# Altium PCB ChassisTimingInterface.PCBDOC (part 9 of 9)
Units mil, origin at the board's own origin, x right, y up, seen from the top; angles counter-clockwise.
Board outline 7007.87 x 4368.85 mil, 10 copper layers (Top Layer, Int1 (GND), Int2 (Sign), Int3 (Sign), Int4 (PWR), Int5 (GND), Int6 (Sign), Int7 (Sign), Int8 (GND), Bottom Layer), stack 54.89 mil thick; 537 components, 525 nets, 2288 pads, 1306 vias.
Unrouted connection lines stored in the file: 373.
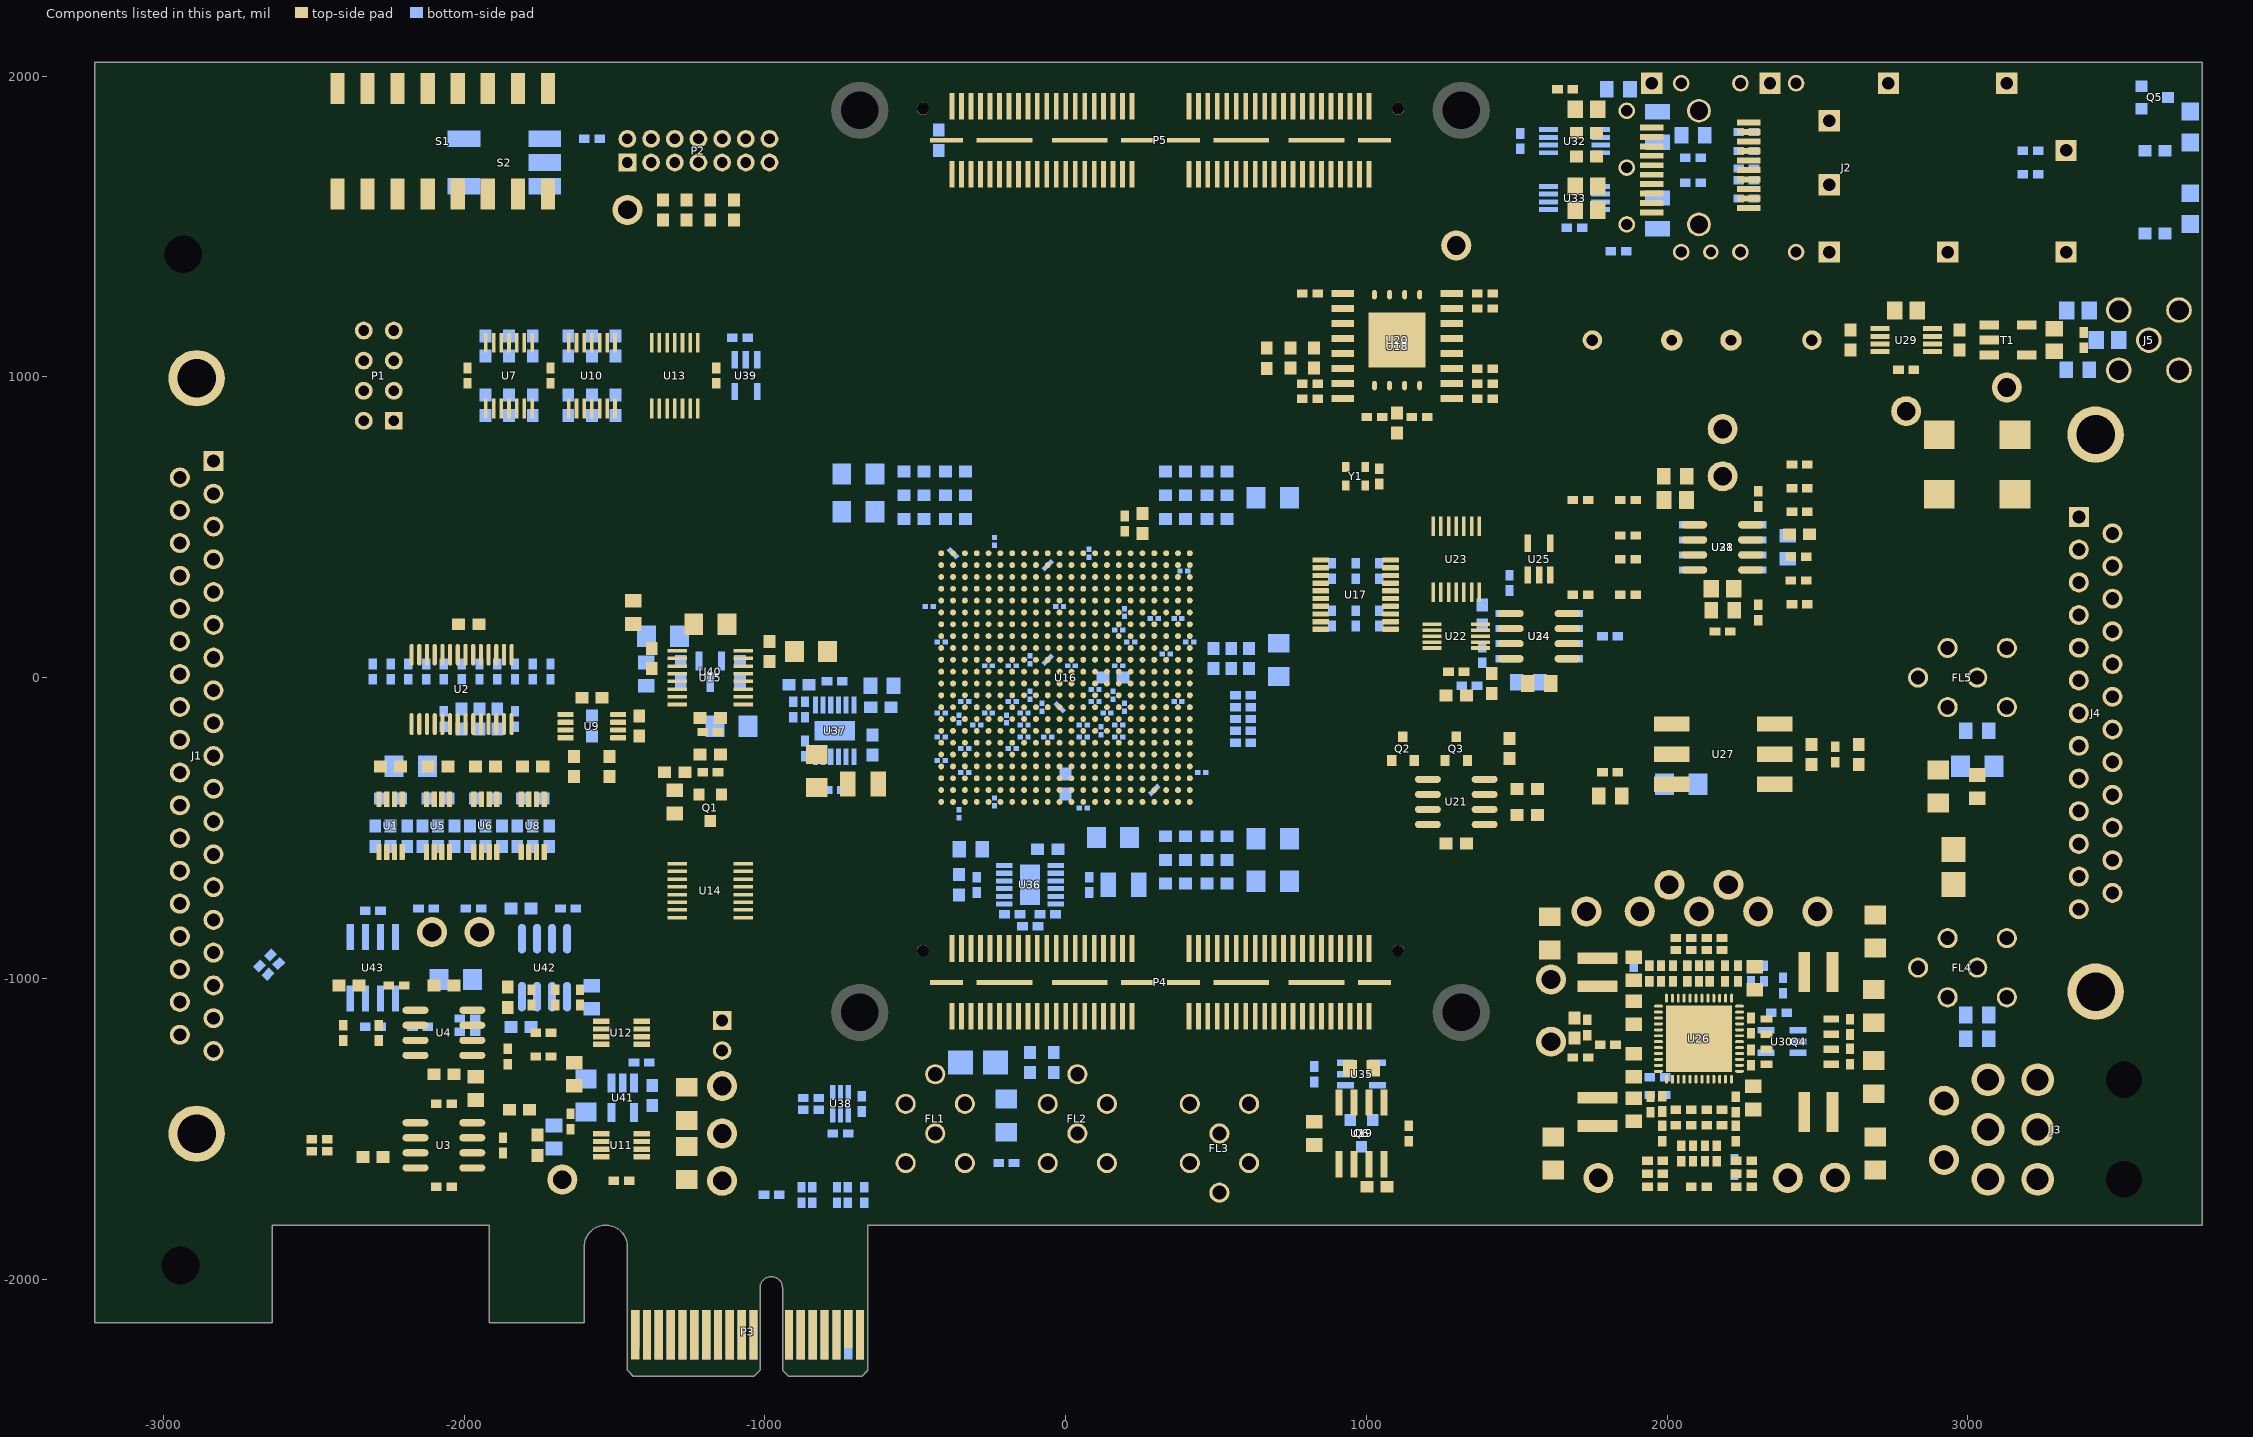
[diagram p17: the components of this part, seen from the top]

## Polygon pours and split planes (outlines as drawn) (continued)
no net on Bottom Layer "NONET_L10_P092" (solid, pour order 92): 2299.21,-1082.68
NetC129_2 on Bottom Layer "NETC129_2_L10_P044" (solid, pour order 44): 169.29,-748.03 169.29,-622.05 137.8,-590.55 137.8,-472.44 64.9,-472.44 64.9,-681.1 90.55,-681.1 106.3,-696.85 106.3,-748.03
GND on Bottom Layer "GND_L10_P053" (solid, pour order 53): -877.95,-125.98 -877.95,-145.67 -921.26,-188.98 -921.26,-228.35 -846.46,-228.35 -807.09,-188.98 -807.09,-145.67 -838.58,-145.67 -858.27,-125.98
XADCVCC on Bottom Layer "XADCVCC_L10_P090" (solid, pour order 90): -94.49,-74.8 -94.49,-51.18 ccw(c-114.17,-51.18) -114.17,-31.5 -432.79,-31.5 cw(c-432.79,121.25) -540.8,13.24 ccw(c-613.37,-59.32) -613.38,43.31 -870.08,43.31 cw(c-870.08,59.05) -885.83,59.3 ccw(c-1383.11,67) -885.83,74.8 -883.46,74.8 -593.14,74.8 cw(c-593.13,-16.96) -528.23,47.92 -507.68,27.36 ccw(c-432.12,102.92) -432.12,-3.94 -46.57,-3.94 cw(c-46.56,-68.83) -0.68,-22.95 cw(c-40.31,-62.59) 15.75,-62.6 15.75,-74.8 cw(c0,-74.81) 0,-90.55 -78.74,-90.55 cw(c-78.74,-74.8)
XADCGND on Bottom Layer "XADCGND_L10_P087" (solid, pour order 87): -110.24,-122.05 -110.24,-169.29 ccw(c-94.49,-169.3) -94.49,-185.04 -1.62,-185.04 ccw(c-1.62,-152.55) 21.37,-175.51 62.55,-134.26 ccw(c23.38,-95.14) 78.74,-95.14 78.74,3.94 ccw(c58.98,3.94) 58.98,23.7 -381.95,23.7 -414.51,23.7 cw(c-414.53,107.22) -481.18,56.89 ccw(c-592.84,-27.27) -539.84,102.12 ccw(c-601.12,-46.64) -601.31,114.25 -870,114.25 ccw(c-870.02,98.44) -885.83,98.43 -885.83,80.01 -585.35,80.12 cw(c-585.28,-8.37) -522.7,54.19 -499.35,30.85 ccw(c-434.34,95.91) -434.34,3.94 -43.25,3.94 cw(c-43.24,-62.91) 23.6,-62.92 23.6,-74.82 cw(c-7.78,-74.84) -7.8,-106.23 -94.41,-106.22 ccw(c-94.42,-122.04)
no net on Bottom Layer "NONET_L10_P086" (solid, pour order 86): -19.69,-59.06
no net on Bottom Layer "NONET_L10_P085" (solid, pour order 85): -944.88,118.11
GND on Bottom Layer "GND_L10_P084" (solid, pour order 84): 858.27,417.32 984.25,543.31 1200.79,543.31 1200.79,354.33 1102.36,354.33 1102.36,374.02 858.27,374.02
GND on Bottom Layer "GND_L10_P082" (solid, pour order 82): 311.02,688.98 311.02,704.72 354.33,748.03 362.2,748.03 362.2,688.98
no net on Bottom Layer "NONET_L10_P081" (solid, pour order 81): -421.26,755.91
no net on Bottom Layer "NONET_L10_P080" (solid, pour order 80): -807.09,582.68
AGND on Bottom Layer "AGND_L10_P076" (solid, pour order 76): 2244.09,370.08 2200.79,326.77 2200.79,271.65 2314.96,157.48 2381.89,157.48 2437.01,212.6 2437.01,409.45 2366.14,409.45 2326.77,370.08
AGND on Bottom Layer "AGND_L10_P074" (solid, pour order 74): 1803.15,157.48 1787.4,173.23 1712.6,173.23 1712.6,102.36 1787.4,102.36 1803.15,118.11
P10V on Bottom Layer "P10V_L10_P073" (solid, pour order 73): 1555.12,590.55 1544.88,590.55 ccw(c1544.88,490.55) 1444.88,490.55 1444.88,330.71 1507.87,330.71 1507.87,484.25 cw(c1555.12,484.25) 1555.12,531.5
P10V on Bottom Layer "P10V_L10_P068" (solid, pour order 68): 2224.41,590.55 ccw(c2224.41,570.87) 2204.72,570.87 2204.72,464.57 ccw(c2224.41,464.57) 2224.41,444.88 2421.26,444.88 ccw(c2421.26,464.57) 2440.94,464.57 2440.94,570.87 ccw(c2421.26,570.87) 2421.26,590.55
no net on Bottom Layer "NONET_L10_P067" (solid, pour order 67): 2224.41,590.55
AGND on Bottom Layer "AGND_L10_P062" (solid, pour order 62): 1287.4,157.48 ccw(c1299.21,157.48) 1299.21,145.67 1318.9,145.67 ccw(c1318.9,157.48) 1330.71,157.48 1330.71,204.72 cw(c1346.46,204.72) 1346.46,220.47 1417.32,220.47 1417.32,271.65 1354.33,271.65 ccw(c1354.33,204.72) 1287.4,204.72
AGND on Bottom Layer "AGND_L10_P057" (solid, pour order 57): 1625.98,11.81 1625.98,-51.18 1570.87,-106.3 1468.5,-106.3 1468.5,-62.99 1535.43,-62.99 1555.12,-43.31 1555.12,11.81
P10V on Bottom Layer "NONET_L10_P054" (solid, pour order 54): 1523.62,-43.32 1523.62,11.81 1562.99,51.18 1594.49,51.18 1594.49,74.78 1429.11,74.78 1417.32,62.99 1350.39,62.99 1350.39,-43.32 1421.26,-43.32 1476.39,-43.32
no net on Bottom Layer "NONET_L10_P047" (solid, pour order 47): -1622.05,-1543.31
no net on Bottom Layer "NONET_L10_P046" (solid, pour order 46): -1559.06,-1303.15
no net on Bottom Layer "NONET_L10_P045" (solid, pour order 45): -1653.54,-1173.23
no net on Bottom Overlay "NONET_L-01_P-001" (solid): -1492.13,-1555.12
P5V on Int7 (Sign) "P5V_L08_P052" (solid, pour order 52): -2637.8,-1653.54 -2637.8,-1051.18 -2326.77,-740.16 -1641.73,-740.16 -1338.58,-1043.31 -1338.58,-1708.66 -1716.54,-1708.66 -1771.65,-1653.54
AVCC1V8 on Int7 (Sign) "AVCC1V8_L08_P079" (solid, pour order 79): 1673.23,-1204.72 1673.23,-1385.83 -279.53,-1385.83 -1527.56,-137.79 -1527.56,177.17 -1358.27,177.17 -1358.27,-66.93 -220.47,-1204.73
no net on Int7 (Sign) "NONET_L08_P078" (solid, pour order 78): 1692.91,-1141.73
N12V on Int2 (Sign) "N12V_L03_P048" (solid, pour order 48): 480.22,-1712.61 480.22,-1122.85 -1259.04,-1122.85 -1641.73,-740.16 -2326.77,-740.16 -2637.8,-1051.18 -2637.8,-1653.54 -1771.65,-1653.54 -1716.54,-1708.66 -1421.26,-1708.66
no net on MultiLayer "NONET_L-01_P-001" (solid): -2255.91,102.36
GND on Int1 (GND) (split plane): 161 vertices, not listed, extent -3208.25,-2302.74 3119.99,2025.92
VREF2V5 on Int1 (GND) (split plane): -1505.99,-1698.73 -1712.42,-1698.73 -1764.63,-1646.52 -1766.69,-1644.95 -1769.08,-1643.95 -1771.65,-1643.62 -2155.43,-1643.62 -2155.43,-998.12 -1505.99,-998.12
VCC2 on Int1 (GND) (split plane): -1309.14,212.42 -1309.14,161.59 -1424.34,46.39 -1425.92,44.33 -1426.91,41.94 -1427.25,39.37 -1427.25,0 -1427.25,-255.91 -1427.25,-369.9 -1539.55,-482.2 -1574.8,-482.2 -2279.35,-482.2 -2387.71,-373.84 -2387.71,58.88 -2200.61,245.98 -1342.69,245.98
EXT12V on Int1 (GND) (split plane): 3297.16,-1303.32 3297.16,-1673.23 3297.16,-1688.8 3259.67,-1726.29 3155.69,-1726.29 2864.26,-1434.86 2864.26,-1067.1 2917.5,-1013.86 3007.7,-1013.86
12V on Int1 (GND) (split plane): 3759.43,-1800.77 -186.92,-1800.77 -186.92,-1441.12 -130.78,-1384.97 -74.63,-1328.82 1476.38,-1328.82 1478.95,-1328.49 1481.34,-1327.49 1483.4,-1325.92 1562.14,-1247.18 1563.72,-1245.12 1564.71,-1242.73 1565.05,-1240.16 1565.05,-944.88 1564.71,-942.31 1563.72,-939.92 1562.82,-938.75 1562.14,-937.86 1325.92,-701.64 1210.71,-586.44 1210.71,-476.55 1263.95,-423.31 2519.69,-423.31 2522.25,-422.97 2524.65,-421.98 2526.7,-420.41 2664.5,-282.61 2684.19,-262.93 2684.19,-262.92 3136.94,189.83 3137.63,190.72 3138.52,191.89 3139.51,194.28 3139.85,196.85 3139.85,255.91 3139.85,968.5 3139.51,971.07 3138.52,973.47 3136.94,975.52 2432.22,1680.25 2430.16,1681.83 2427.77,1682.82 2425.2,1683.16 968.68,1683.16 797.33,1854.51 797.33,2025.92 3759.43,2025.92
XADCVCC on Int1 (GND) (split plane): -817.01,9.93 -1407.4,9.93 -1407.4,35.26 -1295.1,147.55 -817.01,147.55
VCC1V8 on Int1 (GND) (split plane): 777.47,-78.74 777.47,-133.68 251.79,-659.36 181.28,-659.36 29.61,-507.7 29.61,-59.06 29.27,-56.49 28.28,-54.09 26.7,-52.04 24.65,-50.46 22.25,-49.47 19.68,-49.13 -433.07,-49.13 -435.64,-49.47 -438.03,-50.46 -440.09,-52.04 -538.52,-150.46 -540.09,-152.52 -541.09,-154.91 -541.42,-157.48 -541.42,-350.22 -574.98,-383.77 -659.36,-383.77 -659.36,-63.17 -507.7,88.5 777.47,88.5
VCC on Int4 (PWR) (split plane): 3759.43,-1800.77 -657.48,-1800.77 -661.4,-1801.16 -665.17,-1802.3 -668.65,-1804.16 -671.69,-1806.66 -674.19,-1809.7 -676.05,-1813.18 -677.19,-1816.95 -677.58,-1820.87 -677.58,-2294.83 -685.49,-2302.74 -912.94,-2302.74 -920.85,-2294.83 -920.85,-2029.53 -920.86,-2029.38 -921.22,-2023.09 -922.3,-2016.73 -924.08,-2010.54 -926.55,-2004.58 -929.67,-1998.94 -933.4,-1993.68 -937.69,-1988.87 -942.5,-1984.58 -947.76,-1980.85 -953.4,-1977.73 -959.36,-1975.26 -965.55,-1973.48 -971.91,-1972.4 -978.35,-1972.04 -984.78,-1972.4 -991.14,-1973.48 -997.33,-1975.26 -1003.29,-1977.73 -1008.93,-1980.85 -1014.19,-1984.58 -1019,-1988.87 -1023.3,-1993.68 -1027.03,-1998.94 -1030.15,-2004.58 -1032.61,-2010.54 -1034.4,-2016.73 -1035.48,-2023.09 -1035.83,-2029.38 -1035.84,-2029.53 -1035.84,-2294.83 -1043.76,-2302.74 -1428.68,-2302.74 -1436.6,-2294.83 -1436.6,-1892.72 -1436.61,-1892.55 -1436.96,-1884.7 -1438,-1876.75 -1439.74,-1868.92 -1442.15,-1861.27 -1445.22,-1853.86 -1448.92,-1846.75 -1453.23,-1839.98 -1458.11,-1833.62 -1463.53,-1827.71 -1469.45,-1822.29 -1475.81,-1817.41 -1482.57,-1813.1 -1489.69,-1809.39 -1497.1,-1806.32 -1504.75,-1803.91 -1512.58,-1802.18 -1520.53,-1801.13 -1528.54,-1800.78 -1536.56,-1801.13 -1544.51,-1802.18 -1552.34,-1803.91 -1559.99,-1806.32 -1567.4,-1809.39 -1574.51,-1813.1 -1581.28,-1817.41 -1587.64,-1822.29 -1593.55,-1827.71 -1598.97,-1833.62 -1603.85,-1839.98 -1608.16,-1846.75 -1611.87,-1853.86 -1614.94,-1861.27 -1617.35,-1868.92 -1619.08,-1876.75 -1620.13,-1884.7 -1620.47,-1892.55 -1620.49,-1892.72 -1620.49,-2125.57 -1895.26,-2125.57 -1895.26,-1820.87 -1895.64,-1816.95 -1896.79,-1813.18 -1898.64,-1809.7 -1901.14,-1806.66 -1904.19,-1804.16 -1907.66,-1802.3 -1911.43,-1801.16 -1915.35,-1800.77 -2637.8,-1800.77 -2641.72,-1801.16 -2645.49,-1802.3 -2648.96,-1804.16 -2652.01,-1806.66 -2654.51,-1809.7 -2656.36,-1813.18 -2657.51,-1816.95 -2657.89,-1820.87 -2657.89,-2125.57 -3208.25,-2125.57 -3208.25,2025.92 3759.43,2025.92
AVTT on Int4 (PWR) (split plane): -383.94,-137.8 -383.6,-140.36 -382.61,-142.76 -381.04,-144.81 -378.98,-146.39 -376.59,-147.38 -374.02,-147.72 -344.57,-147.72 -344.57,-334.65 -344.57,-816.84 -974.32,-816.84 -974.32,-29.61 -383.94,-29.61
AVCC on Int4 (PWR) (split plane): -187.09,39.37 -187.09,-19.68 -187.09,-177.17 -187.09,-216.54 -187.09,-255.91 -187.09,-816.84 -324.72,-816.84 -324.72,-334.65 -324.72,-137.8 -325.06,-135.23 -326.05,-132.83 -327.63,-130.78 -329.68,-129.2 -332.08,-128.21 -334.65,-127.87 -364.09,-127.87 -364.09,-19.68 -364.43,-17.12 -365.42,-14.72 -367,-12.67 -369.05,-11.09 -371.45,-10.1 -374.02,-9.76 -974.32,-9.76 -974.32,521.57 -187.09,521.57
VCCINT on Int4 (PWR) (split plane): 88.5,-59.06 88.84,-61.62 89.83,-64.02 91.41,-66.07 93.46,-67.65 95.86,-68.64 98.43,-68.98 665.18,-68.98 800.07,-203.87 1545.19,-948.99 1545.19,-1015.75 1545.53,-1018.32 1546.52,-1020.71 1548.1,-1022.77 1587.47,-1062.14 1589.52,-1063.72 1591.92,-1064.71 1594.49,-1065.05 2035.26,-1065.05 2583.53,-1613.32 2612.12,-1641.91 2612.12,-1684.86 2591.41,-1705.58 2582.5,-1714.48 2535.61,-1714.48 2395.73,-1574.6 2395.42,-1572.23 2394.42,-1569.84 2392.85,-1567.78 2390.79,-1566.21 2388.4,-1565.21 2386.03,-1564.9 1995.21,-1174.08 1993.15,-1172.51 1990.76,-1171.51 1988.19,-1171.18 1500.17,-1171.18 1148.75,-819.75 1146.7,-818.17 1144.3,-817.18 1141.73,-816.84 -167.24,-816.84 -167.24,-216.54 -167.24,-177.17 -167.24,-29.61 88.5,-29.61
P10V on Int4 (PWR) (split plane): 1505.82,397.46 1505.82,157.48 1506.16,154.91 1507.15,152.52 1508.73,150.46 1592.43,66.75 1592.43,59.23 1558.88,25.68 1456.87,25.68 1446.94,35.61 1446.94,397.46 1456.87,407.4 1495.89,407.4
VCC1V8 on Int4 (PWR) (split plane): 977.23,-7.02 1355.18,-384.97 1355.19,-384.97 1675.11,-704.9 1675.11,-1045.19 1598.6,-1045.19 1565.05,-1011.64 1565.05,-944.88 1564.71,-942.31 1563.72,-939.92 1562.14,-937.86 814.11,-189.83 676.31,-52.04 674.26,-50.46 671.86,-49.47 669.29,-49.13 108.35,-49.13 108.35,-19.68 108.01,-17.12 107.02,-14.72 105.44,-12.67 103.39,-11.09 100.99,-10.1 98.43,-9.76 -167.24,-9.76 -167.24,521.57 448.64,521.57
GND on Int5 (GND) (split plane): 3759.43,-1800.77 -657.48,-1800.77 -661.4,-1801.16 -665.17,-1802.3 -668.65,-1804.16 -671.69,-1806.66 -674.19,-1809.7 -676.05,-1813.18 -677.19,-1816.95 -677.58,-1820.87 -677.58,-2294.83 -685.49,-2302.74 -912.94,-2302.74 -920.85,-2294.83 -920.85,-2029.53 -920.86,-2029.38 -921.22,-2023.09 -922.3,-2016.73 -924.08,-2010.54 -926.55,-2004.58 -929.67,-1998.94 -933.4,-1993.68 -937.69,-1988.87 -942.5,-1984.58 -947.76,-1980.85 -953.4,-1977.73 -959.36,-1975.26 -965.55,-1973.48 -971.91,-1972.4 -978.35,-1972.04 -984.78,-1972.4 -991.14,-1973.48 -997.33,-1975.26 -1003.29,-1977.73 -1008.93,-1980.85 -1014.19,-1984.58 -1019,-1988.87 -1023.3,-1993.68 -1027.03,-1998.94 -1030.15,-2004.58 -1032.61,-2010.54 -1034.4,-2016.73 -1035.48,-2023.09 -1035.83,-2029.38 -1035.84,-2029.53 -1035.84,-2294.83 -1043.76,-2302.74 -1428.68,-2302.74 -1436.6,-2294.83 -1436.6,-1892.72 -1436.61,-1892.55 -1436.96,-1884.7 -1438,-1876.75 -1439.74,-1868.92 -1442.15,-1861.27 -1445.22,-1853.86 -1448.92,-1846.75 -1453.23,-1839.98 -1458.11,-1833.62 -1463.53,-1827.71 -1469.45,-1822.29 -1475.81,-1817.41 -1482.57,-1813.1 -1489.69,-1809.39 -1497.1,-1806.32 -1504.75,-1803.91 -1512.58,-1802.18 -1520.53,-1801.13 -1528.54,-1800.78 -1536.56,-1801.13 -1544.51,-1802.18 -1552.34,-1803.91 -1559.99,-1806.32 -1567.4,-1809.39 -1574.51,-1813.1 -1581.28,-1817.41 -1587.64,-1822.29 -1593.55,-1827.71 -1598.97,-1833.62 -1603.85,-1839.98 -1608.16,-1846.75 -1611.87,-1853.86 -1614.94,-1861.27 -1617.35,-1868.92 -1619.08,-1876.75 -1620.13,-1884.7 -1620.47,-1892.55 -1620.49,-1892.72 -1620.49,-2125.57 -1895.26,-2125.57 -1895.26,-1820.87 -1895.64,-1816.95 -1896.79,-1813.18 -1898.64,-1809.7 -1901.14,-1806.66 -1904.19,-1804.16 -1907.66,-1802.3 -1911.43,-1801.16 -1915.35,-1800.77 -2637.8,-1800.77 -2641.72,-1801.16 -2645.49,-1802.3 -2648.96,-1804.16 -2652.01,-1806.66 -2654.51,-1809.7 -2656.36,-1813.18 -2657.51,-1816.95 -2657.89,-1820.87 -2657.89,-2125.57 -3208.25,-2125.57 -3208.25,2025.92 3759.43,2025.92
BGND on Int5 (GND) (split plane): -1215.68,-1180.25 -1192.06,-1203.87 -1190,-1205.45 -1187.61,-1206.44 -1185.04,-1206.78 11.64,-1206.78 88.5,-1283.64 88.5,-1302.12 88.5,-1307.09 88.5,-1440.94 88.5,-1496.06 88.84,-1498.63 89.83,-1501.03 91.41,-1503.08 130.78,-1542.45 131.67,-1543.14 132.83,-1544.03 135.23,-1545.02 137.8,-1545.36 204.72,-1545.36 207.29,-1545.02 209.69,-1544.03 211.74,-1542.45 378.13,-1376.07 440.77,-1376.07 553.06,-1488.36 553.06,-1726.29 470.56,-1726.29 470.56,-1562.99 470.56,-1547.24 470.22,-1544.67 469.23,-1542.28 467.65,-1540.22 436.15,-1508.73 434.1,-1507.15 431.7,-1506.16 429.13,-1505.82 370.08,-1505.82 367.51,-1506.16 365.12,-1507.15 363.06,-1508.73 208.49,-1663.3 157.48,-1663.3 155.51,-1663.56 153.54,-1663.3 118.29,-1663.3 -9.76,-1535.26 -9.76,-1338.58 -10.1,-1336.01 -11.09,-1333.62 -11.98,-1332.46 -12.67,-1331.56 -59.91,-1284.32 -61.97,-1282.74 -64.36,-1281.75 -66.93,-1281.41 -1161.42,-1281.41 -1163.99,-1281.75 -1166.38,-1282.74 -1168.44,-1284.32 -1207.81,-1323.69 -1209.38,-1325.74 -1210.38,-1328.14 -1210.71,-1330.71 -1210.71,-1385.83 -1210.38,-1388.4 -1209.38,-1390.79 -1207.81,-1392.85 -1168.44,-1432.22 -1167.54,-1432.9 -1166.38,-1433.79 -1163.99,-1434.79 -1161.42,-1435.12 -1090.73,-1435.12 -1053.23,-1472.62 -1053.23,-1566.75 -1090.73,-1604.25 -1165.35,-1604.25 -1167.92,-1604.58 -1170.32,-1605.58 -1172.37,-1607.15 -1207.81,-1642.59 -1209.38,-1644.64 -1210.38,-1647.04 -1210.71,-1649.61 -1210.71,-1676.99 -1232.46,-1698.73 -1712.42,-1698.73 -1764.63,-1646.52 -1766.69,-1644.95 -1769.08,-1643.95 -1771.65,-1643.62 -2627.87,-1643.62 -2627.87,-1059.23 -2422.11,-853.48 -2318.72,-750.08 -1645.84,-750.08
XADCGND on Int5 (GND) (split plane): -1180.25,209.52 -1089.7,118.96 -1088.8,118.28 -1087.64,117.39 -1085.25,116.4 -1082.68,116.06 -820.95,116.06 -820.95,59.23 -830.88,49.3 -944.88,49.3 -947.45,48.96 -949.85,47.97 -951.9,46.39 -953.48,44.33 -954.47,41.94 -954.81,39.37 -954.81,-19.69 -954.47,-22.25 -953.48,-24.65 -951.9,-26.7 -919.38,-59.23 -919.38,-125.81 -937.18,-143.62 -1035.43,-143.62 -1038,-143.95 -1040.4,-144.95 -1042.45,-146.52 -1102.54,-206.61 -1177.17,-206.61 -1179.73,-206.95 -1182.13,-207.94 -1184.19,-209.52 -1602.54,-627.87 -2291.16,-627.87 -2387.71,-531.32 -2387.71,58.88 -2200.61,245.98 -1216.71,245.98
AGND on Int5 (GND) (split plane): 3179.05,566.75 3179.05,118.11 3179.05,63.17 3083.53,-32.35 2515.57,-600.31 1815.14,-600.31 1683.16,-468.33 1683.16,-275.59 1682.82,-273.02 1681.83,-270.63 1680.93,-269.46 1680.25,-268.57 1562.14,-150.46 1560.08,-148.88 1557.69,-147.89 1555.12,-147.55 1323.01,-147.55 1269.77,-94.31 1269.77,212.42 1362.38,305.03 1909.45,305.03 1912.02,305.37 1914.41,306.36 1916.47,307.94 1995.21,386.68 1996.1,387.84 1996.79,388.74 1997.08,389.44 1997.78,391.13 1998.12,393.7 1998.12,665.18 2110.41,777.47 2968.33,777.47
VDD on Int8 (GND) (split plane): 3759.43,-1800.77 -657.48,-1800.77 -661.4,-1801.16 -665.17,-1802.3 -668.65,-1804.16 -671.69,-1806.66 -674.19,-1809.7 -676.05,-1813.18 -677.19,-1816.95 -677.58,-1820.87 -677.58,-2294.83 -685.49,-2302.74 -912.94,-2302.74 -920.85,-2294.83 -920.85,-2029.53 -920.86,-2029.38 -921.22,-2023.09 -922.3,-2016.73 -924.08,-2010.54 -926.55,-2004.58 -929.67,-1998.94 -933.4,-1993.68 -937.69,-1988.87 -942.5,-1984.58 -947.76,-1980.85 -953.4,-1977.73 -959.36,-1975.26 -965.55,-1973.48 -971.91,-1972.4 -978.35,-1972.04 -984.78,-1972.4 -991.14,-1973.48 -997.33,-1975.26 -1003.29,-1977.73 -1008.93,-1980.85 -1014.19,-1984.58 -1019,-1988.87 -1023.3,-1993.68 -1027.03,-1998.94 -1030.15,-2004.58 -1032.61,-2010.54 -1034.4,-2016.73 -1035.48,-2023.09 -1035.83,-2029.38 -1035.84,-2029.53 -1035.84,-2294.83 -1043.76,-2302.74 -1428.68,-2302.74 -1436.6,-2294.83 -1436.6,-1892.72 -1436.61,-1892.55 -1436.96,-1884.7 -1438,-1876.75 -1439.74,-1868.92 -1442.15,-1861.27 -1445.22,-1853.86 -1448.92,-1846.75 -1453.23,-1839.98 -1458.11,-1833.62 -1463.53,-1827.71 -1469.45,-1822.29 -1475.81,-1817.41 -1482.57,-1813.1 -1489.69,-1809.39 -1497.1,-1806.32 -1504.75,-1803.91 -1512.58,-1802.18 -1520.53,-1801.13 -1528.54,-1800.78 -1536.56,-1801.13 -1544.51,-1802.18 -1552.34,-1803.91 -1559.99,-1806.32 -1567.4,-1809.39 -1574.51,-1813.1 -1581.28,-1817.41 -1587.64,-1822.29 -1593.55,-1827.71 -1598.97,-1833.62 -1603.85,-1839.98 -1608.16,-1846.75 -1611.87,-1853.86 -1614.94,-1861.27 -1617.35,-1868.92 -1619.08,-1876.75 -1620.13,-1884.7 -1620.47,-1892.55 -1620.49,-1892.72 -1620.49,-2125.57 -1895.26,-2125.57 -1895.26,-1820.87 -1895.64,-1816.95 -1896.79,-1813.18 -1898.64,-1809.7 -1901.14,-1806.66 -1904.19,-1804.16 -1907.66,-1802.3 -1911.43,-1801.16 -1915.35,-1800.77 -2637.8,-1800.77 -2641.72,-1801.16 -2645.49,-1802.3 -2648.96,-1804.16 -2652.01,-1806.66 -2654.51,-1809.7 -2656.36,-1813.18 -2657.51,-1816.95 -2657.89,-1820.87 -2657.89,-2125.57 -3208.25,-2125.57 -3208.25,2025.92 3759.43,2025.92
N5V on Int8 (GND) (split plane): -1368.2,-1027.73 -1368.2,-1698.73 -1712.42,-1698.73 -1764.63,-1646.52 -1766.69,-1644.95 -1769.08,-1643.95 -1771.65,-1643.62 -2627.87,-1643.62 -2627.87,-1059.23 -2318.72,-750.08 -1645.84,-750.08

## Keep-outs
Top Layer:
  rectangle: -3228.35,1208.66 -2728.35,2013.78
  rectangle: -657.48,-1820.87 3779.53,-1781.5
  region: -3228.35,-2147.65 -2637.8,-2147.65 ccw(c-2637.8,-2145.67) -2635.81,-2145.67 -2635.81,-1822.85 -1917.34,-1822.85 -1917.34,-2009.84 ccw(c-1915.35,-2009.84) -1915.35,-2011.83 -1600.39,-2011.83 ccw(c-1600.39,-2009.84) -1598.41,-2009.84 ccw(c-1600.39,-2009.84) -1598.41,-2009.82 -1598.41,-1892.72 cw(c-1528.54,-1892.72) -1458.68,-1892.72 ccw(c-1456.69,-1892.72) -1454.71,-1892.72 -1454.71,-1781.5 ccw(c-1456.69,-1781.5) -1456.69,-1779.51 -3228.35,-1779.51 ccw(c-3228.35,-1781.5) -3230.33,-1781.5 -3230.33,-2145.67 ccw(c-3228.35,-2145.67)
Bottom Layer:
  rectangle: -657.48,-1820.87 3372.05,-1781.5
  rectangle: -3228.35,1208.66 -2728.35,2013.78
  region: -3228.35,-2147.65 -2637.8,-2147.65 ccw(c-2637.8,-2145.67) -2635.81,-2145.67 -2635.81,-1822.85 -1917.34,-1822.85 -1917.34,-2009.84 ccw(c-1915.35,-2009.84) -1915.35,-2011.83 -1600.39,-2011.83 ccw(c-1600.39,-2009.84) -1598.41,-2009.84 ccw(c-1600.39,-2009.84) -1598.41,-2009.82 -1598.41,-1892.72 cw(c-1528.54,-1892.72) -1458.68,-1892.72 ccw(c-1456.69,-1892.72) -1454.71,-1892.72 -1454.71,-1781.5 ccw(c-1456.69,-1781.5) -1456.69,-1779.51 -3228.35,-1779.51 ccw(c-3228.35,-1781.5) -3230.33,-1781.5 -3230.33,-2145.67 ccw(c-3228.35,-2145.67)
Top Solder:
  rectangle: -1915.35,-2145.67 -1600.39,-2009.84
Bottom Solder:
  rectangle: -1915.35,-2145.67 -1600.39,-2009.84
KeepOutLayer:
  rectangle: -1915.35,-2145.67 -1600.39,-2009.84

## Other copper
Top Layer:
  rectangle net NetC67_1: 2460.63,-322.83 2574.8,-263.78
  rectangle net AGND: 2460.63,-248.03 2574.8,-185.04
  rectangle net NetC38_2: 1818.9,-421.26 1874.02,-299.21
  rectangle net 12V: 1846.46,-1277.06 1917.78,-1259.84
  rectangle net SENSE.SENS_18_P: 1704.72,-952.76 1917.32,-862.2
  rectangle net AGND: 2216.54,141.73 2330.71,165.35
  rectangle net N5V: -1909.45,-1125.98 -1826.77,-1070.87
  rectangle net GND: -2019.69,893.7 -1960.63,996.06
  rectangle net NetC25_2: -751.97,-397.64 -669.29,-311.02
  rectangle net NetC25_2: -885.83,-397.64 -696.85,-334.65
  rectangle net GND: -834.65,-244.09 -779.53,-141.73
  rectangle net GND: -921.26,-287.4 -779.53,-224.41
  rectangle net VDD: -822.83,19.69 -783.46,59.06
  rectangle net GND: 2240.16,-976.38 2275.59,-917.32
  rectangle net AVCC1V8: 1566.93,-1210.63 1661.42,-1149.1
  rectangle net AVCC1V8: 1566.93,-1156.49 1678.52,-1110.24
  rectangle net GND: 2078.74,-972.44 2129.92,-905.51
  rectangle net GND: 1968.5,-972.44 1992.13,-901.57
  rectangle net VDD: 1811.02,-1251.97 1826.77,-1205.71
  rectangle net GND: 2216.54,-1559.06 2259.84,-1523.62
  rectangle net GND: 1720.47,-1277.06 1795.28,-1171.26
  rectangle net AVCC1V8: 1656,-1156.49 1751.97,-1110.24
  rectangle net GND: 2062.99,-1452.76 2149.61,-1421.26
  rectangle net GND: 1952.76,-1559.06 1996.06,-1523.62
  rectangle net GND: 1859.52,-1372.04 1918.57,-1303.15
  rectangle net 12V: 1843.01,-1175.19 1916.83,-1129.42
  rectangle net GND: 1862.2,-1052.16 1917.32,-986.22
  rectangle net GND: 2259.84,-1474.41 2314.96,-1415.35
  rectangle net 12V: 2259.84,-1379.92 2314.96,-1316.93
  rectangle net 12V: 2263.78,-1078.74 2318.9,-1015.75
  rectangle net VCC: 1566.93,-1744.09 1834.65,-1590.55
  rectangle net GND: 1859.52,-1421.26 1918.57,-1353.34
  rectangle net GND: 1862.2,-1096.46 1917.32,-1030.81
  rectangle net SENSE.SENS_10_P: 2515.75,-1578.74 2755.91,-1326.77
  rectangle net VCCINT: 2507.87,-1744.09 2755.91,-1594.49
  rectangle net SENSE.SENS_25_P: 2514.76,-1098.43 2755.91,-851.86
  rectangle net SENSE.SENS_33_P: 1566.93,-1577.89 1917.57,-1450.79
  rectangle net NetC49_1: 1566.93,-1441.92 1843.85,-1283.45
  rectangle net NetC48_1: 1700.79,-1082.68 1846.46,-965.54
  rectangle net VDD: 2448.82,-834.65 2755.91,-726.38
  rectangle net AGND: 1543.31,106.3 1606.3,173.23
  rectangle net P10V: 2212.6,496.06 2358.27,586.61
  rectangle net GND: 1598.43,311.02 1649.61,374.02
  rectangle net AGND: 2854.33,556.1 2956.69,858.27
  rectangle net GND: -1464.57,240.16 -1409.45,303.15
  rectangle net AVCC1V8: -1480.32,102.36 -1409.45,200.79
  rectangle net AGND: 1311.02,-106.3 1561.02,-31.5
  rectangle net VCC1V8: -647.75,-397.64 -570.87,-311.02
  rectangle net XADCGND: -1535.43,-374.02 -1496.06,-307.09
  rectangle net VCC2: -1653.54,-374.02 -1614.17,-307.09
  rectangle net AGND: 2287.4,125.98 2354.33,208.66
  rectangle net AGND: 2279.53,602.36 2326.77,685.04
  rectangle net AGND: 2448.82,598.43 2531.5,661.42
  rectangle net AGND: 2448.82,681.1 2531.5,736.22
  rectangle net GND: 1562.99,1929.13 1653.54,1984.25
  rectangle net AGND: 1748.03,-421.26 1803.15,-299.21
  rectangle net NetC35_2: 1669.29,1696.85 1724.41,1988.19
  rectangle net GND: 1744.09,1858.27 1818.9,1921.26
  rectangle net GND: 1665.35,1523.62 1724.41,1665.35
  rectangle net XADCGND: -1259.84,-275.59 -1192.91,-236.22
  rectangle net VCC: -1157.48,141.73 -1070.87,212.6
  rectangle net VCC2: -1385.83,141.73 -1204.72,212.6
  rectangle net VCC2: -1972.44,153.54 -1905.51,200.79
  rectangle net XADCGND: -2062.99,153.54 -1996.06,200.79
  rectangle net GND: 2704.72,1188.98 2783.46,1251.97
  rectangle net GND: 2704.72,996.06 2787.4,1051.18
  rectangle net VCC: -1740.16,1011.81 -1685.04,1133.86
  rectangle net VCC: -2019.69,1011.81 -1960.63,1133.86
  rectangle net GND: -1740.16,874.02 -1685.04,996.06
  rectangle net VCC: -1196.85,893.7 -1133.86,996.06
  rectangle net GND: -1192.91,1011.81 -1133.86,1133.86
  rectangle net BGND: -1661.42,-1425.2 -1606.3,-1334.65
  rectangle net VREF2V5: -1724.41,-1145.67 -1669.29,-1070.87
  rectangle net VREF2V5: -1728.35,-1311.02 -1606.3,-1244.09
  rectangle net BGND: -2287.4,-1045.21 -2232.28,-968.5
  rectangle net BGND: -2370.08,-1045.21 -2314.96,-968.5
  rectangle net BGND: -2055.12,-1350.39 -1933.07,-1291.34
  rectangle net P5V: -2153.54,-1346.46 -2078.74,-1291.34
  rectangle net BGND: -1641.73,-1055.12 -1586.61,-976.38
  rectangle net BGND: -1724.41,-1055.12 -1669.29,-976.38
  rectangle net BGND: -1803.15,-1055.12 -1748.03,-976.38
  rectangle net BGND: -1881.89,-1051.18 -1826.77,-976.38
  rectangle net VREF2V5: -2059.06,-1448.82 -1933.07,-1381.89
  rectangle net BGND: -1897.64,-1641.73 -1842.52,-1562.99
  rectangle net P5V: -1673.23,-1562.99 -1618.11,-1484.25
  rectangle net BGND: -1803.15,-1468.5 -1606.3,-1409.45
  rectangle net N5V: -1881.89,-1464.57 -1826.77,-1385.83
  rectangle net P5V: -2291.34,-1645.67 -2236.22,-1560.58
  rectangle net BGND: -2472.44,-1625.98 -2314.96,-1560.58
  rectangle net VREF2V5: -1566.93,-1700.79 -1484.25,-1645.67
  rectangle net BGND: -1468.5,-1700.79 -1386.91,-1645.67
  rectangle net GND: 791.34,-1500 862.2,-1401.57
  rectangle net GND: 1114.17,-1507.87 1169.29,-1429.13
  rectangle net 12V: 1114.17,-1602.36 1169.29,-1523.62
  rectangle net VDD: 740.16,913.39 807.09,992.13
  region: -251.97,-1633.86
Int6 (Sign):
  rectangle net BUS12V: -1429.13,-2086.61 -1318.9,-2007.87
Bottom Layer:
  rectangle net VCC1V8: 472.44,-27.56 744.09,35.43
  rectangle net VCC: 858.27,216.54 1070.87,334.65
  rectangle net GND: 1751.97,1389.76 1830.71,1444.88
  rectangle net BGND: -1881.89,-1188.98 -1822.83,-1125.98
  rectangle net N12V: -1401.57,-1480.31 -1346.46,-1401.57
  rectangle net GND: 472.44,82.68 744.09,145.67
  region net VCC1V8: 287.4,-748.03 287.4,-618.11 216.54,-618.11 216.54,-748.03
  rectangle net GND: -704.72,-204.72 -622.05,-149.61
  region net AVCC: -224.41,-606.3 -224.41,-543.31 -303.15,-543.31 -303.15,-606.3
  rectangle net GND: -921.26,-279.53 -889.76,-185.04
  rectangle net GND: -921.26,-228.35 -850.39,-185.04
  region net GND: -62.99,-842.52 -62.99,-767.72 -110.24,-767.72 -110.24,-842.52
  region net GND: -275.59,-681.1 -275.59,-614.17 -381.89,-614.17 -381.89,-681.1
  region net GND: -314.96,-543.31 -381.89,-543.31 -381.89,-681.1 -314.96,-681.1
  rectangle net AVCC: -220.47,-846.46 -185.04,-779.53
  region net GND: 287.4,-586.61 287.4,-476.38 177.17,-476.38 177.17,-586.61
  rectangle net GND: -574.8,-55.12 -523.62,-31.5
  rectangle net VCC: 2307.09,-976.38 2337.6,-905.51
  rectangle net AVCC1V8: -1476.38,102.36 -1366.14,173.23
  rectangle net BGND: -1657.48,-1397.64 -1559.06,-1303.15
  rectangle net GND: 3303.15,1192.91 3354.33,1279.53
  rectangle net GND: 3303.15,968.5 3354.33,1051.18
  rectangle net GND: 685.04,-700.79 732.28,-657.48
  rectangle net GND: -1043.31,-196.85 -996.06,-153.54
  rectangle net GND: 307.09,507.87 362.2,736.22
  rectangle net VDD: 377.95,507.87 421.26,736.22
  rectangle net GND: 448.82,472.44 492.13,736.22
  rectangle net VDD: 515.75,507.87 559.06,736.22
  rectangle net VDD: 574.8,559.06 665.35,641.73
  rectangle net GND: 712.6,559.06 803.15,641.73
  rectangle net GND: -366.14,507.87 -303.15,736.22
  rectangle net VDD: -421.26,507.87 -377.95,736.22
  rectangle net GND: -492.13,480.32 -448.82,736.22
  rectangle net VDD: -559.06,507.87 -515.75,736.22
  rectangle net VDD: -665.35,637.8 -574.8,720.47
  rectangle net VDD: -665.35,519.69 -574.8,582.68
  rectangle net GND: -807.09,519.69 -712.6,582.68
  rectangle net GND: -807.09,637.8 -712.6,720.47
  rectangle net GND: 688.98,-559.06 736.22,-527.56
  rectangle net VCCINT: 578.74,-692.91 622.05,-653.54
  rectangle net VCCINT: 578.74,-559.06 629.92,-527.56
  rectangle net VREG: -2141.73,-350.39 -2102.36,-307.09
  rectangle net GND: 1862.2,-1051.18 1917.32,-1035.43
  rectangle net GND: 1881.89,-1051.18 1897.64,-1011.81
  rectangle net GND: 1880.03,-1013.78 1901.57,-1012.33
  rectangle net GND: 2090.55,-944.88 2122.05,-921.26
  rectangle net VCCINT: 1929.13,-972.44 1952.76,-913.39
  rectangle net GND: 1972.44,-972.44 1988.19,-905.59
  rectangle net GND: 2240.16,-976.38 2275.59,-917.32
  rectangle net XADC.XADC_REF_P: -1155.51,23.62 -1114.17,86.61
  rectangle net P10V: 1543.31,531.5 2240.16,590.55
  rectangle net P10V: 1444.88,322.83 1507.87,405.51
  rectangle net VCC: 1015.75,300.68 1165.35,326.77
  rectangle net GND: 858.27,98.43 1070.87,177.17
  rectangle net XADCGND: -1232.28,-196.85 -1129.92,-55.12
  rectangle net XADCGND: -1421.26,-74.8 -1366.14,-11.81
  rectangle net XADCGND: -1421.26,-98.43 -1275.59,-55.12
  rectangle net XADCVCC: -1299.21,39.37 -1259.84,89.57
  rectangle net XADCVCC: -1421.26,53.15 -1259.84,74.74
  rectangle net AVTT: -671.55,-118.11 -625.98,-0.66
  rectangle net AVTT: -976.38,-149.61 -893.7,-114.17
  rectangle net XADCVCC: -1248.03,23.62 -1208.66,86.61
  rectangle net XADCGND: -1299.21,-98.43 -1062.99,-7.87
  rectangle net VCC2: -1594.49,-149.61 -1531.5,-106.3
  rectangle net XADCGND: -1618.11,-216.54 -1555.12,-173.23
  rectangle net AGND: 1543.31,102.36 1606.3,173.23
  rectangle net AGND: 1393.7,220.47 1417.32,318.9
  rectangle net GND: 1751.97,1929.13 1822.83,1984.25
  rectangle net GND: 1602.36,1468.5 1685.04,1523.62
  rectangle net XADCGND: -2086.61,31.56 -1694.28,74.8
  rectangle net XADCGND: -1791.34,31.5 -1692.91,118.11
  rectangle net VCC: 2070.87,-389.76 2161.42,-318.9
  rectangle net VCC: 1925.2,1851.18 2039.37,1909.45
  rectangle net VCC: 1925.2,1464.57 2039.37,1519.69
  rectangle net BGND: -2295.28,-799.21 -2220.47,-751.97
  rectangle net BGND: -1401.57,-1377.95 -1346.46,-1303.15
  rectangle net P12V: -2240.16,-905.51 -2192.91,-818.9
  rectangle net P12V: -2413.39,-905.51 -2366.14,-818.9
  rectangle net P5V: -2114.17,-1023.62 -2051.18,-929.13
  rectangle net BGND: -2003.94,-1023.62 -1940.94,-929.13
  rectangle net BGND: -2137.8,-1185.04 -2059.06,-1145.67
  rectangle net BGND: -2370.08,-992.13 -2314.96,-968.5
  rectangle net BGND: -1881.89,-1000 -1826.77,-976.38
  rectangle net BGND: -1881.89,-1188.98 -1846.46,-976.38
  rectangle net VREF2V5: -1799.21,-1188.98 -1673.23,-1125.98
  rectangle net P5V: -1618.11,-1165.35 -1578.74,-1078.74
  rectangle net BGND: -1641.73,-1007.87 -1547.24,-976.38
  rectangle net BGND: -1728.35,-1511.81 -1673.23,-1413.39
  rectangle net P5V: -1728.35,-1590.55 -1622.05,-1543.31
  rectangle net N5V: -1401.57,-1295.28 -1366.14,-1236.22
  rectangle net N5V: -1633.86,-1480.31 -1496.06,-1413.39
  region: -2137.8,-350.39
  region: -2137.8,-350.39
  region net SENS15: -255.59,-1629.92 -255.59,-1570.87 -204.72,-1570.87 -204.72,-1629.92
Int1 (GND) (plane layer: these items are gaps in the copper):
  lines w19.68: -196.85,-1818.9 -196.85,-1437.01 -137.8,-1377.95 ; 787.4,2047.24 787.4,1850.39 964.57,1673.23 2425.2,1673.23 3129.92,968.5 3129.92,255.91 3129.92,196.85 2677.17,-255.91 2657.48,-275.59 2519.69,-413.39 2370.08,-413.39 1259.84,-413.39 1200.79,-472.44 1200.79,-590.55 1318.9,-708.66 1555.12,-944.88 1555.12,-1240.16 1476.38,-1318.9 -78.74,-1318.9 -137.8,-1377.95 ; -1574.8,-492.13 -1535.43,-492.13 -1417.32,-374.02 -1417.32,-255.91 -1417.32,0 ; -1574.8,-492.13 -1574.8,-492.13 ; -1574.8,-492.13 -2283.46,-492.13 -2397.64,-377.95 -2397.64,62.99 -2204.72,255.91 -1870.08,255.91 -1622.05,255.91 -1338.58,255.91 -1299.21,216.54 -1299.21,157.48 ; -1417.32,0 -1417.32,39.37 -1299.21,157.48 ; -1417.32,0 -807.09,0 -807.09,157.48 -1240.16,157.48 -1299.21,157.48 ; -137.8,-1377.95 -137.8,-1377.95 ; -2165.35,-1653.54 -1942.91,-1653.54 -1771.65,-1653.54 -1716.54,-1708.66 -1496.06,-1708.66 -1496.06,-988.19 -2165.35,-988.19 -2165.35,-1653.54 ; -669.29,-393.7 -669.29,-59.06 -511.81,98.43 787.4,98.43 787.4,-78.74 787.4,-137.8 255.91,-669.29 177.17,-669.29 19.68,-511.81 19.68,-59.06 -433.07,-59.06 -531.5,-157.48 -531.5,-354.33 -570.87,-393.7 -669.29,-393.7 ; 2854.33,-1438.98 3151.57,-1736.22 3228.35,-1736.22 3263.78,-1736.22 3307.09,-1692.91 3307.09,-1673.23 3307.09,-1299.21 3011.81,-1003.94 2913.39,-1003.94 2854.33,-1062.99 2854.33,-1438.98
Int4 (PWR) (plane layer: these items are gaps in the copper):
  lines w19.68: -885.83,-19.68 -984.25,-19.68 ; -334.65,-334.65 -334.65,-826.77 ; -177.17,-255.91 -177.17,-177.17 -177.17,531.5 ; -177.17,-216.54 -177.17,-826.77 ; 216.49,-59.06 405.51,-59.06 649.61,-59.06 ; 2385.83,-1574.8 2385.83,-1578.74 2531.5,-1724.41 2555.12,-1724.41 ; 2401.57,-1594.49 1988.19,-1181.1 1614.17,-1181.1 1496.06,-1181.1 1141.73,-826.77 807.09,-826.77 -177.17,-826.77 ; 2539.37,-1724.41 2586.61,-1724.41 2622.05,-1688.98 ; 2598.43,-1712.6 2622.05,-1688.98 ; 3779.53,-1299.21 3779.53,-897.64 ; 3779.53,-338.58 3779.53,1240.16 ; -984.25,-19.68 -984.25,531.5 -177.17,531.5 ; -984.25,-19.68 -772.64,-19.68 -413.39,-19.68 -374.02,-19.68 -374.02,-137.8 -334.65,-137.8 -334.65,-826.77 ; -984.25,-19.68 -984.25,-826.77 -334.65,-826.77 ; -334.65,-826.77 -177.17,-826.77 ; -177.17,531.5 452.76,531.5 984.25,0 ; -177.17,531.5 -177.17,39.37 -177.17,-19.68 -137.8,-19.68 -19.69,-19.68 59.06,-19.68 98.43,-19.68 98.43,-59.06 137.8,-59.06 649.61,-59.06 ; 649.61,-59.06 669.29,-59.06 807.09,-196.85 1555.12,-944.88 1555.12,-1015.75 1594.49,-1055.12 2039.37,-1055.12 2590.55,-1606.3 2622.05,-1637.8 2622.05,-1641.73 2622.05,-1688.98 ; 984.25,0 984.25,0 ; 984.25,0 1362.2,-377.95 1685.04,-700.79 1685.04,-1055.12 ; 1685.04,-1055.12 1685.04,-1055.12 ; 1437.01,31.5 1452.76,15.75 1511.81,15.75 1562.99,15.75 1602.36,55.12 1602.36,70.87 1515.75,157.48 1515.75,401.57 1500,417.32 1452.76,417.32 1437.01,401.57 1437.01,31.5
Int5 (GND) (plane layer: these items are gaps in the copper):
  lines w19.68: -1094.49,-1196.85 15.75,-1196.85 98.43,-1279.53 98.43,-1307.09 ; -1090.55,-1196.85 -1185.04,-1196.85 -1208.66,-1173.23 ; -657.48,-1820.87 -472.44,-1820.87 ; 98.43,-1302.12 98.43,-1440.94 ; 153.54,-1673.23 145.67,-1673.23 114.17,-1673.23 -19.69,-1539.37 -19.69,-1338.58 -66.93,-1291.34 -1137.8,-1291.34 -1161.42,-1291.34 -1200.79,-1330.71 -1200.79,-1385.83 -1161.42,-1425.2 -1086.61,-1425.2 -1043.31,-1468.5 -1043.31,-1570.87 -1086.61,-1614.17 -1165.35,-1614.17 -1200.79,-1649.61 -1200.79,-1681.1 -1228.35,-1708.66 -1279.53,-1708.66 -1507.87,-1708.66 -1573.82,-1708.66 -1716.54,-1708.66 -1771.65,-1653.54 -2413.39,-1653.54 -2637.8,-1653.54 -2637.8,-1055.12 -2429.13,-846.46 ; 157.48,-1673.23 212.6,-1673.23 370.08,-1515.75 429.13,-1515.75 460.63,-1547.24 460.63,-1562.99 460.63,-1736.22 535.43,-1736.22 562.99,-1736.22 562.99,-1484.25 444.88,-1366.14 385.83,-1366.14 374.02,-1366.14 204.72,-1535.43 137.8,-1535.43 98.43,-1496.06 ; -2429.13,-846.46 -2322.83,-740.16 -2149.61,-740.16 -1641.73,-740.16 -1208.66,-1173.23 ; -2429.13,-846.46 -2429.13,-846.46 ; -1208.66,-1173.23 -1208.66,-1173.23 ; 98.43,-1496.06 98.43,-1440.94 ; 98.43,-1496.06 98.43,-1440.94 ; -2397.64,-535.43 -2397.64,62.99 -2204.72,255.91 -1417.32,255.91 -1318.9,255.91 -1212.6,255.91 -1173.23,216.54 -1082.68,125.98 -957.11,125.98 -811.02,125.98 -811.02,55.12 -826.77,39.37 -901.57,39.37 -944.88,39.37 -944.88,-19.69 -909.45,-55.12 -909.45,-129.92 -933.07,-153.54 -1035.43,-153.54 -1098.43,-216.54 -1177.17,-216.54 -1598.43,-637.8 -2295.28,-637.8 -2397.64,-535.43 ; -1393.7,-988.19 -1393.7,-988.19 ; 1259.84,-98.43 1318.9,-157.48 1555.12,-157.48 1673.23,-275.59 1673.23,-472.44 1811.02,-610.24 2519.69,-610.24 3090.55,-39.37 3188.98,59.06 3188.98,118.11 3188.98,570.87 2972.44,787.4 2106.3,787.4 1988.19,669.29 1988.19,393.7 1909.45,314.96 1358.27,314.96 1259.84,216.54 1259.84,-98.43
Int8 (GND) (plane layer: these items are gaps in the copper):
  lines w19.68: -1374.02,-1708.66 -1358.27,-1708.66 -1358.27,-1023.62 -1641.73,-740.16 -2322.83,-740.16 -2637.8,-1055.12 -2637.8,-1653.54 -1771.65,-1653.54 -1716.54,-1708.66 -1367.98,-1708.66 ; 1834.65,-1822.83 3779.53,-1822.83 3779.53,-1338.58 3779.53,-964.57

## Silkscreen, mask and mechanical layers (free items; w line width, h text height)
Top Overlay:
  rectangle: -2405.51,374.02 -1185.04,669.29
  text "D2000329" at -3212.6,1763.78 h180
  text "rev 1" at -3212.6,1649.61 h120
  text "serial" at -1433.07,681.1 h120
PCI-SIG Outline:
  lines w3.94: -3228.35,-2145.67 -3228.35,2053.15 3779.53,2053.15 3779.53,-1820.87 -657.48,-1820.87 -657.48,-2303.15 -677.17,-2322.83 -921.26,-2322.83 -940.94,-2303.15 -940.94,-2029.53 ccw(c-978.35,-2029.53) -1015.75,-2029.53 -1015.75,-2303.15 -1035.43,-2322.83 -1437.01,-2322.83 -1456.69,-2303.15 -1456.69,-1892.72 ccw(c-1528.54,-1892.72) -1600.39,-1892.72 -1600.39,-2145.67 -1915.35,-2145.67 -1915.35,-1820.87 -2637.8,-1820.87 -2637.8,-2145.67 -3228.35,-2145.67
Mechanical7:
  lines w3.94: -3228.35,-1781.5 -3228.35,-2145.67 -2637.8,-2145.67 -2637.8,-1820.87 -1915.35,-1820.87 -1915.35,-2009.84 -1600.39,-2009.84 -1600.39,-1892.72 cw(c-1528.54,-1892.72) -1456.69,-1892.72 -1456.69,-1781.5 ; -3218.5,-1830.71 -1446.85,-1830.71

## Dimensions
-3228.35,-2322.83 to -3228.35,2053.15 on PCI-SIG Dimensions
-3228.35,-2145.67 to -3228.35,2053.15 on PCI-SIG Dimensions
-3228.35,2053.15 to 3779.53,2066.93 on PCI-SIG Dimensions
